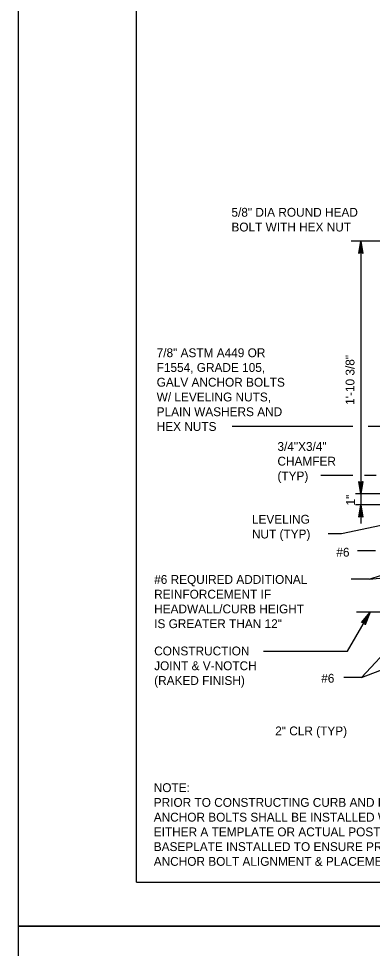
# Model space of a CAD drawing. Extents: x 641054 to 641910, y 298137 to 299325.
# Drawn here: x 641054.5 to 641174.5, y 298723.9 to 299039.1 of the extents above; entities that cross this region are included whole.
import ezdxf

# ---------------------------------------------------------------- set-up
doc = ezdxf.new("R2010")
doc.units = 0
for name, color, linetype in [('1', 7, 'Continuous'), ('2', 7, 'Continuous'), ('PLT-BNDY', 7, 'Continuous')]:
    doc.layers.add(name, color=color, linetype=linetype)

msp = doc.modelspace()

# ---------------------------------------------------------------- linework, layer by layer
at = {"layer": '1'}
for p, q in [((641196.92, 298963.63), (641167.34, 298963.63)), ((641170.62, 298963.63), (641170.62, 298867.93)), ((641167.85, 298900.88), (641126.95, 298900.88)), ((641180.8, 298900.88), (641173.07, 298900.88)), ((641167.85, 298884.27), (641156.98, 298884.27)), ((641175.75, 298884.27), (641171.85, 298884.27)), ((641180.09, 298878.04), (641168.79, 298878.04)), ((641183.24, 298874.22), (641168.79, 298874.22)), ((641201.71, 298872.47), (641164.04, 298864.39)), ((641164.04, 298864.39), (641159.47, 298864.39)), ((641183.99, 298837.87), (641169.06, 298837.87))]:
    msp.add_line(p, q, dxfattribs=at)
msp.add_lwpolyline([(641137.6, 298824.63), (641166.08, 298824.63), (641173.75, 298837.87)], dxfattribs=at)
at = {"layer": '2'}
for p, q in [((641094.49, 298746.38), (641094.49, 299310.38)), ((641175.55, 298858.64), (641169.48, 298858.64)), ((641173.4, 298849.09), (641238.3, 298855.51)), ((641173.4, 298849.09), (641193.08, 298855.38)), ((641173.4, 298849.09), (641167.27, 298849.09)), ((641170.83, 298815.69), (641238.97, 298842.2)), ((641170.83, 298815.69), (641194.22, 298840.92)), ((641170.83, 298815.69), (641164.76, 298815.69)), ((641094.49, 298746.38), (641880.49, 298746.38))]:
    msp.add_line(p, q, dxfattribs=at)
for points in [[(641170.12, 298959.66), (641170.41, 298959.81), (641170.62, 298963.63), (641170.12, 298959.66), (641169.95, 298959.45), (641170.62, 298963.63), (641170.81, 298959.81), (641171.09, 298959.67), (641170.62, 298963.63), (641171.28, 298959.45), (641171.09, 298959.67)], [(641171.12, 298882.01), (641170.83, 298881.87), (641170.62, 298878.04), (641171.12, 298882.01), (641171.29, 298882.22), (641170.62, 298878.04), (641170.43, 298881.86), (641170.15, 298882), (641170.62, 298878.04), (641169.96, 298882.22), (641170.15, 298882)], [(641170.12, 298870.24), (641170.41, 298870.39), (641170.62, 298874.22), (641170.12, 298870.24), (641169.95, 298870.04), (641170.62, 298874.22), (641170.81, 298870.39), (641171.09, 298870.25), (641170.62, 298874.22), (641171.28, 298870.04), (641171.09, 298870.25)], [(641171.12, 298834.41), (641171.47, 298834.4), (641173.75, 298837.87), (641171.12, 298834.41), (641170.85, 298834.32), (641173.75, 298837.87), (641171.85, 298834.18), (641172.04, 298833.89), (641173.75, 298837.87), (641172.1, 298833.59), (641172.04, 298833.89)]]:
    msp.add_lwpolyline(points, dxfattribs=at)
at = {"layer": 'PLT-BNDY'}
for points in [[(641054.49, 299325.38), (641895.49, 299325.38), (641895.49, 298731.38), (641054.49, 298731.38)], [(641054.49, 298731.38), (641895.49, 298731.38), (641895.49, 298137.38), (641054.49, 298137.38)]]:
    msp.add_lwpolyline(points, close=True, dxfattribs=at)

# ---------------------------------------------------------------- texts
at = {"layer": '2'}
for s, height, p in [('5/8" DIA ROUND HEAD', 3.0001, (641126.69, 298971.95)), ('BOLT WITH HEX NUT', 3.0001, (641126.69, 298966.95)), ('7/8" ASTM A449 OR', 3.0001, (641101.33, 298924.33)), ('F1554, GRADE 105,', 3.0001, (641101.33, 298919.33)), ('GALV ANCHOR BOLTS', 3.0001, (641101.33, 298914.33)), ('W/ LEVELING NUTS,', 3.0001, (641101.33, 298909.33)), ('PLAIN WASHERS AND', 3.0001, (641101.33, 298904.33)), ('HEX NUTS', 3, (641101.33, 298899.33)), ('3/4"X3/4"', 3, (641142.3, 298892.56)), ('CHAMFER', 3, (641142.3, 298887.56)), ('(TYP)', 3, (641142.3, 298882.56)), ('LEVELING', 3, (641133.64, 298867.87)), ('NUT (TYP)', 3, (641133.64, 298862.87)), ('#6', 3, (641162.27, 298856.71)), ('#6 REQUIRED ADDITIONAL', 3.0001, (641100.48, 298847.47)), ('REINFORCEMENT IF ', 3.0001, (641100.48, 298842.47)), ('HEADWALL/CURB HEIGHT', 3.0001, (641100.48, 298837.47)), ('IS GREATER THAN 12"', 3.0001, (641100.48, 298832.47)), ('CONSTRUCTION', 3.0001, (641100.48, 298823.22)), ('JOINT & V-NOTCH', 3.0001, (641100.48, 298818.21)), ('#6', 3, (641157.14, 298813.97)), ('(RAKED FINISH)', 3.0001, (641100.48, 298813.21)), ('2" CLR (TYP)', 3, (641141.53, 298796.11)), ('NOTE:', 3, (641100.34, 298776.88)), ('PRIOR TO CONSTRUCTING CURB AND DECK,', 3, (641100.34, 298771.88)), ('ANCHOR BOLTS SHALL BE INSTALLED WITH', 3, (641100.34, 298766.88)), ('EITHER A TEMPLATE OR ACTUAL POST W/', 3, (641100.34, 298761.88)), ('BASEPLATE INSTALLED TO ENSURE PROPER', 3, (641100.34, 298756.88)), ('ANCHOR BOLT ALIGNMENT & PLACEMENT.', 3, (641100.34, 298751.88))]:
    msp.add_text(s, height=height, dxfattribs=at).set_placement(p)
for s, p in [('1\'-10 3/8"', (641168.42, 298908.17)), ('1"', (641168.6, 298874.05))]:
    msp.add_text(s, height=3, rotation=90, dxfattribs=at).set_placement(p)

doc.saveas('drawing.dxf')
